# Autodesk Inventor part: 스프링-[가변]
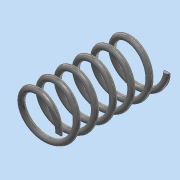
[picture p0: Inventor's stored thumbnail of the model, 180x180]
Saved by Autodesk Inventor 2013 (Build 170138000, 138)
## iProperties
Created: 2017-06
Part Number: 스프링-[가변]
Material: 강철, 탄소
Document SubType Name: Modeling
Designer: Administrator
Density: 7.87 g/cm^3
Mass: 7.32473 g
Surface Area: 18.9743 cm^2
Volume: 0.930716 cm^3
Author: Administrator
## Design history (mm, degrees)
sketch "스케치1"
  geometry: L1 (0, 0)-(8, 0); L2 (8, 0)-(8, 38); L3 (8, 38)-(0, 38); L4 (0, 38)-(0, 0); C1 r 1 at (8, 0)
  constraints: 8 end point, 2 parallel, 1 centre point, 1 coincident, 1 horizontal, 1 perpendicular
  dimensions: "d0" = 38 distance of L1.end L2.end (derived); "d2" = 16 diameter of L2 L4; "d3" = 2 diameter of C1
feature "코일1" sketch "스케치1" pitch "d4" = 10; turns "d6" = 6; dims "d5" = 38 (= d0), "d7" = 0, angle "d8" = 90 deg, angle "d9" = 90 deg, "d10" = 0, "d11" = 0
sketch "스케치2"
  geometry: L1 (-15, 0)-(15, 0); L2 (15, 0)-(15, 38); L3 (15, 38)-(-15, 38); L4 (-15, 38)-(-15, 0); 7 further points
  constraints: 8 end point, 4 horizontal alignment, 2 horizontal, 2 midpoint, 2 vertical alignment, 1 parallel, 1 perpendicular
  dimensions: "d12" = 30 distance of L2.end L3.end
extrude "돌출1" sketch "스케치2" stored distance "d14" = 50; taper "d15" = 0 deg
node "솔리드1"
node "투영된 루프1"
